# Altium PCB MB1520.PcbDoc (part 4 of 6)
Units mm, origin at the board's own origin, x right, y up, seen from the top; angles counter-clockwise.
Board outline 159 x 88 mm, 6 copper layers (Top Layer, Signal Layer 1, Signal Layer 2, Signal Layer 3, Signal Layer 4, Bottom Layer), stack 1.572 mm thick; 473 components, 377 nets, 1832 pads, 1378 vias.
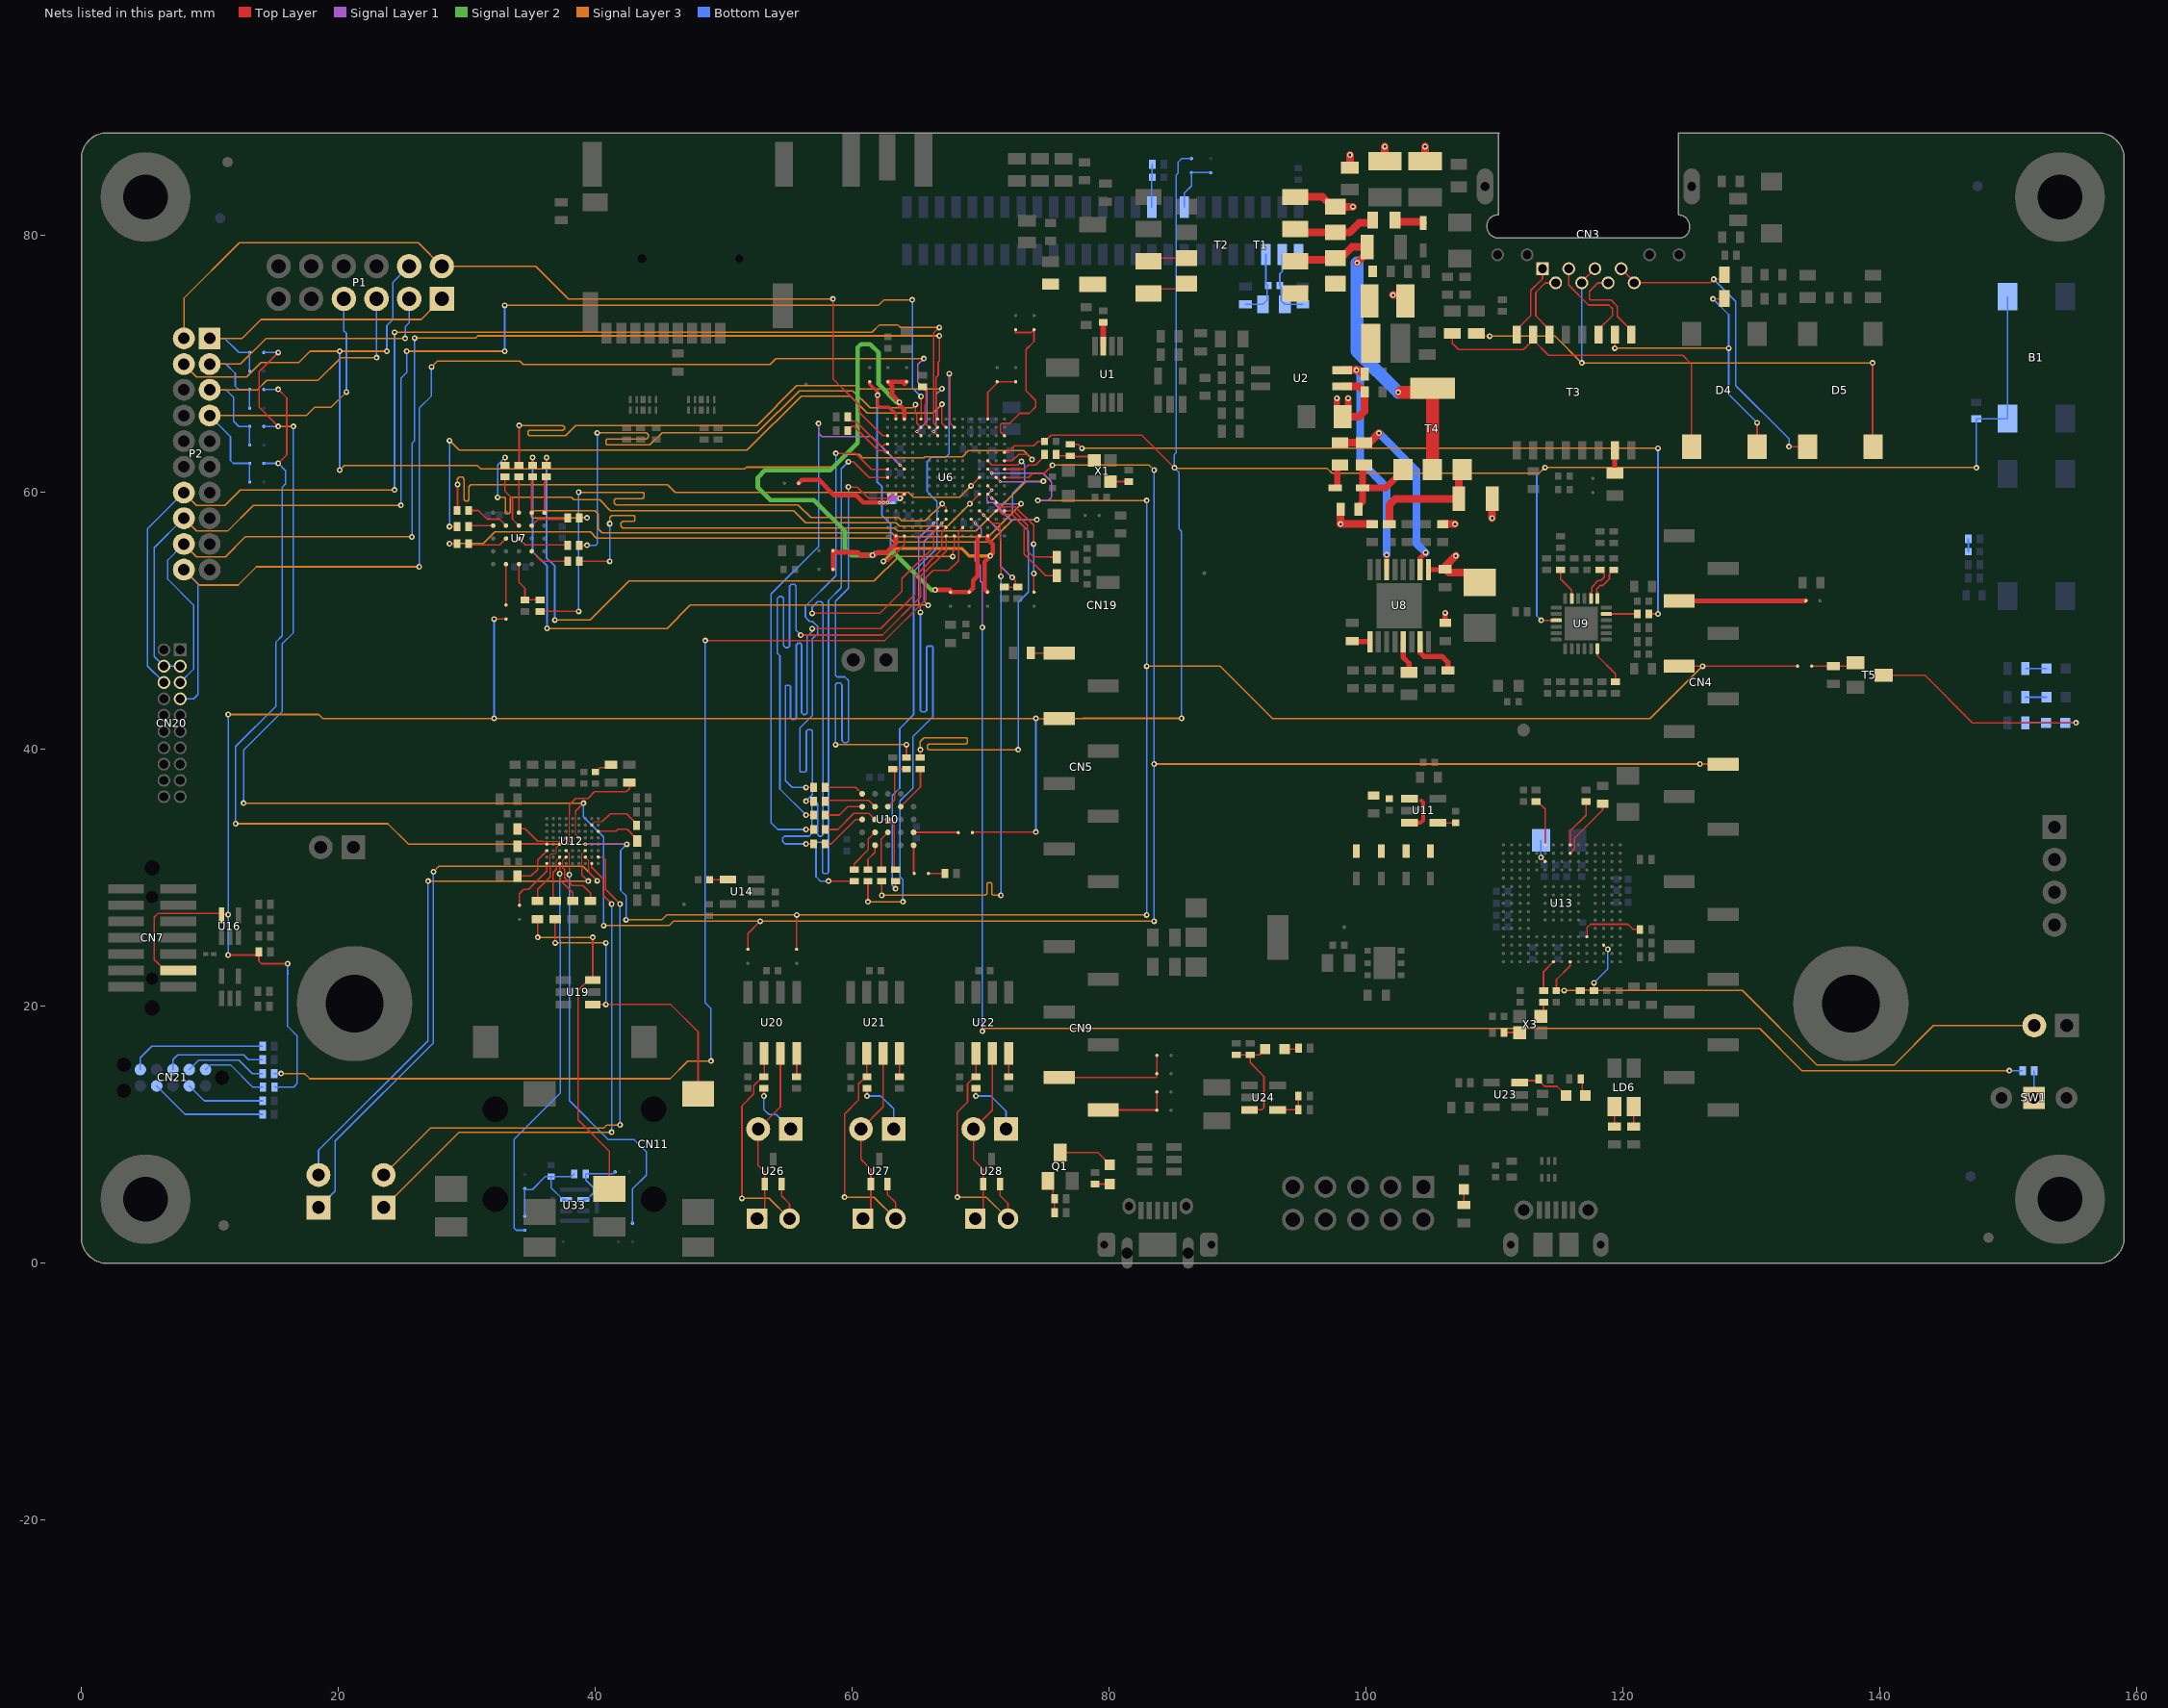
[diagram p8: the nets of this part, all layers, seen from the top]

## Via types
v1: diameter 0.45, hole 0.2, Top Layer to Bottom Layer, tented both sides, 1099 vias
v2: diameter 0.25, hole 0.1, Top Layer to Signal Layer 1, tented both sides, 217 vias
v3: diameter 0.25, hole 0.1, Signal Layer 4 to Bottom Layer, tented both sides, 53 vias
v4: diameter 0.6, hole 0.3, Top Layer to Bottom Layer, tented both sides, 9 vias

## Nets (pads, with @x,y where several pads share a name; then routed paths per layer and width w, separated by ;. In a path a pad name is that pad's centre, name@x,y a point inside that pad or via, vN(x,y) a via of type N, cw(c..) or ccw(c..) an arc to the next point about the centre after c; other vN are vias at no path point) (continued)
NetC69_2: C69.2 R85.2 | length 1.4
  Top Layer w0.12: C69.2@40.025,38.25 40.375,38.6 41,38.6 R85.2@41.225,38.825
NetC71_2: C71.2 U13.J14 | length 4.9
  Top Layer w0.127: U13.J14@115.883,31.927 116.225,32.269 116.225,33.1 118.411,35.286 C71.2@118.411,35.764
NetC73_1: C73.1 C75.2 D8.2 D9.2 D10.2 D11.2 U11.1 U11.3 | length 2.7
  Top Layer w0.3: U11.3@103.386,34.289 104.214,34.289 104.425,34.5 104.425,35.875 104.275,36.025
NetC76_2: C76.2 U11.4 | length 1.4
  Top Layer w0.12: U11.4@105.586,34.289 C76.2@106.986,34.289
NetC78_1: C78.1 U12.E6 | length 4.3
  Top Layer w0.09: 35.945,32.875 37.475,32.875 U12.E6@37.725,33.125
  Top Layer w0.1: C78.1@33.95,33.825 34.55,33.825 35.5,32.875 35.945,32.875
NetC79_2: C79.2 U12.F1 | length 3.5
  Top Layer w0.1: U12.F1@40.225,33.625 41.605,33.625 41.755,33.775 42.475,33.775 43.275,32.975 C79.2@43.275,32.875
NetC80_2: C80.2 U12.D9 | length 2.3
  Top Layer w0.1: C80.2@33.95,32.45 34.125,32.625 U12.D9@36.225,32.625
NetC84_2: C84.2 U12.C9 | length 3.5
  Top Layer w0.1: C84.2@33.95,30.15 35,30.15 35.5,30.65 35.5,31.4 U12.C9@36.225,32.125
NetC85_2: C85.2 U14.4 | length 1.4
  Top Layer w0.12: C85.2@48.9,29.875 U14.4@50.325,29.875
NetC89_1: C89.1 U12.D7 | length 5.3
  Top Layer w0.09: 36.475,30.8 36.475,31.775 36.575,31.875 36.875,31.875 36.975,31.975 36.975,32.375 U12.D7@37.225,32.625
  Top Layer w0.1: C89.1@35.5,28.2 35.5,29.1 36.475,30.075 36.475,30.8
NetC89_2: C89.2 CN11.4 U19.6 | length 27
  Top Layer w0.12: C89.2@35.5,26.8 35.525,26.775 v1(35.525,25.375) ; v1(39.8,25.375) U19.6@39.8,22.05 39.45,22.05 38.65,21.25 38.65,11.175 41.1,8.725 CN11.4@41.1,5.8
  Signal Layer 3 w0.12: v1(35.525,25.375) v1(39.8,25.375)
NetC90_1: C90.1 U12.B7 | length 3.7
  Top Layer w0.09: 36.975,30.8 36.975,31.375 U12.B7@37.225,31.625
  Top Layer w0.1: C90.1@36.875,28.2 36.7,28.375 36.7,30.425 36.975,30.7 36.975,30.8
NetC90_2: C90.2 CN11.6 U19.4 | length 24.5
  Top Layer w0.12: v1(36.875,24.95) C90.2@36.875,26.8 ; U19.4@39.8,20.15 45.875,20.15 48,18.025 CN11.6@48,13.2
  Signal Layer 3 w0.12: v1(36.875,24.95) v1(40.825,24.95)
  Bottom Layer w0.12: v1(40.825,20.15) v1(40.825,24.95)
NetC91_2: C91.2 SB37.2 U12.A7 | length 33.3
  Top Layer w0.1: U12.A7@37.225,31.125 37.225,29.875 38.25,28.85 C91.2@38.25,28.2
  Bottom Layer w0.1: 37.225,27.5 v1(37.225,30.325)
  Bottom Layer w0.12: SB37.2@34.512,2.577 33.848,2.577 33.675,2.75 33.675,9.65 37.28,13.255 37.28,25.118 37.225,25.173 37.225,27.5
NetC92_2: C92.2 U12.B6 | length 4.9
  Top Layer w0.09: 37.475,30.8 37.475,31.375 U12.B6@37.725,31.625
  Top Layer w0.1: 37.475,30.8 37.6,30.675 37.6,30 38.2,29.4 39.05,29.4 39.625,28.825 C92.2@39.625,28.2
NetC104_2: C104.2 JP3.2 U13.J1 | length 43.5
  Top Layer w0.12: C104.2@114.811,21.239 v1(115.411,21.239)
  Top Layer w0.127: C104.2@114.811,21.239 114.811,22.086 115.883,23.158 U13.J1@115.883,23.477
  Signal Layer 3 w0.12: v1(115.411,21.239) 129.286,21.239 135.075,15.45 141.1,15.45 144.167,18.517 JP3.2@152.007,18.517
NetC117_2: C117.2 CN19.32 R136.1 | length 3.3
  Bottom Layer w0.127: CN19.32@83.31,82.217 83.31,84.485 C117.2@83.35,84.525 R136.1@83.35,85.55
NetC118_1: C118.1 C119.2 CN19.45 R138.2 | length 5.5
  Bottom Layer w0.127: R138.2@90.6,74.65 C119.2@91.975,74.65 92.3,74.975 92.3,76.025 C118.1@92.375,76.1 92.2,76.275 CN19.45@92.2,78.531
NetC118_2: C118.2 C119.1 CN19.47 CN19.49 R137.2 | length 6.8
  Bottom Layer w0.127: CN19.49@94.74,78.531 CN19.47@93.47,78.531 93.47,77.195 93.275,77 C118.2@93.275,76.1 93.4,75.975 93.4,74.925 C119.1@93.675,74.65 R137.2@95.075,74.65
NetC130_1: C130.1 SB11.2 U6.E15 U6.F13 | length 10.6
  Top Layer w0.3: v1(63.725,59.55) U6.F13@64.05,59.875
  Top Layer w0.35: SB11.2@55.825,60.725 56.075,60.975 57.425,60.975 58.6,59.8 60.3,59.8 60.875,59.225 v2(62.15,59.225) v2(62.45,59.225) v2(62.75,59.225)
  Signal Layer 1 w0.35: v2(62.15,59.225) v2(62.45,59.225) v2(62.75,59.225) 63.075,59.55 v1(63.725,59.55)
  Bottom Layer w0.45: C130.1@63.025,59.55 v1(63.725,59.55)
NetC138_1: C138.1 R140.1 | length 1
  Bottom Layer w0.12: C138.1@146.875,55.4 R140.1@146.875,56.4
NetC142_2: C142.2 U13.F13 | length 1.8
  Top Layer w0.12: v1(113.608,31.602) U13.F13@113.933,31.277
  Bottom Layer w0.1: v1(113.608,31.602) 113.608,32.908 C142.2@113.625,32.925
NetC158_1: C158.1 R154.2 SB36.1 SB37.1 U33.1 | length 8.9
  Bottom Layer w0.12: SB37.1@34.512,3.677 SB36.1@34.512,5.819 34.581,5.75 35.1,5.75 36.098,6.748 C158.1@36.549,6.748 ; U33.1@37.724,4.973 37.477,4.973 36.549,5.901 C158.1@36.549,6.748 ; R154.2@38.36,6.965 38.143,6.748 C158.1@36.549,6.748
NetCN3_1: CN3.1 T3.16 | length 5.9
  Top Layer w0.13: T3.16@111.741,72.299 111.741,72.691 112.821,73.771 112.821,75.725 113.73,76.634 CN3.1@113.73,77.425
NetCN3_2: CN3.2 T3.14 | length 5.6
  Top Layer w0.13: T3.14@114.281,72.299 114.281,72.669 113.202,73.748 113.202,75.567 113.959,76.325 CN3.2@114.75,76.325
NetCN3_3: CN3.3 T3.11 | length 7.9
  Top Layer w0.13: CN3.3@115.77,77.425 115.77,76.141 117.311,74.6 118.9,74.6 119.171,74.329 119.171,73.771 118.091,72.691 T3.11@118.091,72.299
NetCN3_4: CN3.4 CN3.5 D5.2 R15.2 | length 46.1
  Top Layer w0.12: R15.2@108.586,72.389 108.801,72.175 v1(109.625,72.175) ; CN3.4@116.79,76.325 116.79,76.405 CN3.5@117.81,77.425 ; v1(139.425,70.085) 139.425,63.611 D5.2@139.461,63.574
  Signal Layer 3 w0.12: v1(109.625,72.175) 114.7,72.175 v1(116.79,70.085) v1(139.425,70.085)
  Bottom Layer w0.12: v1(116.79,70.085) CN3.4@116.79,76.325
NetCN3_6: CN3.6 T3.9 | length 7.4
  Top Layer w0.13: CN3.6@118.83,76.325 118.05,76.325 117.375,75.65 117.375,75.075 117.469,74.981 119.058,74.981 119.552,74.487 119.552,73.723 120.631,72.644 T3.9@120.631,72.299
NetCN3_7: CN3.7 CN3.8 D5.1 R9.2 | length 25.7
  Top Layer w0.12: CN3.7@119.85,77.425 120.87,76.405 CN3.8@120.87,76.325 126.775,76.325 v1(127.05,76.6) 127.529,76.6 R9.2@127.888,76.959 ; v1(132.923,63.574) D5.1@134.361,63.574
  Bottom Layer w0.12: v1(127.05,76.6) 128.775,74.875 128.775,68.325 132.923,64.177 v1(132.923,63.574)
NetCN4_8: CN4.8 SB23.1 | length 9.9
  Top Layer w0.127: CN4.8@124.372,51.564 CN4.8@124.375,51.567
  Top Layer w0.35: CN4.8@124.372,51.564 134.189,51.564 SB23.1@134.225,51.6
NetCN5_1: CN5.1 R72.2 | length 2.2
  Top Layer w0.12: R72.2@73.911,47.514 76.098,47.514 CN5.1@76.112,47.5
NetCN9_5: CN9.5 SB31.2 SB32.2 | length 9.3
  Top Layer w0.12: CN9.5@76.112,14.48 83.63,14.48 83.711,14.561 SB32.2@83.711,14.764 SB31.2@83.711,16.189
NetCN9_6: CN9.6 SB33.2 SB34.2 | length 5.6
  Top Layer w0.12: CN9.6@79.541,11.94 83.685,11.94 SB34.2@83.711,11.914 SB33.2@83.711,13.339
NetCN12_1: CN12.1 U12.B3 | length 45.5
  Top Layer w0.09: U12.B3@39.225,31.625 39.475,31.375 39.475,30.8
  Top Layer w0.1: 39.475,30.8 39.475,30.45 v1(40.15,29.775)
  Signal Layer 3 w0.12: v1(27.4,30.475) 27.825,30.9 33.2,30.9 39.025,30.9 v1(40.15,29.775)
  Bottom Layer w0.12: CN12.1@18.453,4.343 19.75,5.64 19.75,9.525 27.4,17.175 v1(27.4,30.475)
NetCN12_2: CN12.2 U12.C3 | length 41.5
  Top Layer w0.09: 38.975,30.85 38.975,31.875 U12.C3@39.225,32.125
  Top Layer w0.1: 38.975,30.85 38.975,30.225 v1(39.45,29.75)
  Signal Layer 3 w0.12: v1(26.975,29.75) 33.2,29.75 v1(39.45,29.75)
  Bottom Layer w0.12: CN12.2@18.453,6.883 18.453,8.803 26.975,17.325 v1(26.975,29.75)
NetCN13_1: CN13.1 U12.A2 | length 41.7
  Top Layer w0.1: U12.A2@39.725,31.125 39.725,30.825 40.6,29.95 40.6,28.65 v1(41.275,27.975)
  Signal Layer 3 w0.12: CN13.1@23.533,4.343 29.39,10.2 v1(41.275,10.2)
  Bottom Layer w0.1: 41.275,27.5 v1(41.275,27.975)
  Bottom Layer w0.12: v1(41.275,10.2) 41.275,27.5
NetCN13_2: CN13.2 U12.B1 | length 41.8
  Top Layer w0.09: U12.B1@40.225,31.625 40.625,31.625 40.8,31.45
  Top Layer w0.1: 40.8,31.45 40.8,29.1 v1(41.925,27.975)
  Signal Layer 3 w0.12: CN13.2@23.533,6.883 27.2,10.55 40.675,10.55 40.9,10.775 v1(41.925,10.775)
  Bottom Layer w0.1: 41.925,27.5 v1(41.925,27.975)
  Bottom Layer w0.12: v1(41.925,10.775) 41.925,27.5
NetCN16_1: CN16.1 JP4.2 U20.7 U26.1 | length 14.1
  Top Layer w0.12: CN16.1@52.58,3.475 53.2,4.095 U26.1@53.2,6.175 53.2,7.1 52.68,7.62 JP4.2@52.68,10.45 54.41,12.18 U20.7@54.41,16.35
NetCN16_2: CN16.2 R119.1 U20.6 U26.2 | length 19.4
  Top Layer w0.12: v1(51.41,5.06) 51.41,12.265 52.335,13.19 52.335,13.835 53.025,14.525 R119.1@53.125,14.525 53.14,14.54 U20.6@53.14,16.35 ; U26.2@54.5,6.175 54.5,5.25 55.12,4.63 CN16.2@55.12,3.475
  Signal Layer 3 w0.12: v1(51.41,5.06) 53.535,5.06 CN16.2@55.12,3.475
NetCN17_1: CN17.1 JP5.2 U21.7 U27.1 | length 14.2
  Top Layer w0.12: CN17.1@60.83,3.475 61.45,4.095 U27.1@61.45,6.175 61.45,7.325 60.68,8.095 JP5.2@60.68,10.45 62.41,12.18 U21.7@62.41,16.35
NetCN17_2: CN17.2 R121.1 U21.6 U27.2 | length 19.6
  Top Layer w0.12: v1(59.4,5.15) 59.4,11.625 60.5,12.725 60.5,13.975 61.05,14.525 R121.1@61.15,14.525 61.14,14.535 U21.6@61.14,16.35 ; U27.2@62.75,6.175 62.75,5.35 63.37,4.73 CN17.2@63.37,3.475
  Signal Layer 3 w0.12: v1(59.4,5.15) 61.695,5.15 CN17.2@63.37,3.475
NetCN18_1: CN18.1 JP6.2 U22.7 U28.1 | length 14.1
  Top Layer w0.12: CN18.1@69.58,3.475 70.2,4.095 U28.1@70.2,6.175 70.2,7.325 69.43,8.095 JP6.2@69.43,10.45 70.91,11.93 U22.7@70.91,16.35
NetCN18_2: CN18.2 R123.1 U22.6 U28.2 | length 19.5
  Top Layer w0.12: v1(68.175,5.15) 68.175,11.75 68.975,12.55 68.975,13.975 69.525,14.525 R123.1@69.625,14.525 69.64,14.54 U22.6@69.64,16.35 ; U28.2@71.5,6.175 71.5,5.275 72.12,4.655 CN18.2@72.12,3.475
  Signal Layer 3 w0.12: v1(68.175,5.15) 70.445,5.15 CN18.2@72.12,3.475
NetCN19_36: CN19.36 SB43.1 SB44.1 | length 4.4
  Bottom Layer w0.12: CN19.36@85.85,82.217 85.85,83.325 86.4,83.875 SB44.1@86.4,84.9 SB43.1@87.9,84.9
NetCN21_2: CN21.2 R152.2 | length 6.2
  Bottom Layer w0.12: CN21.2@8.395,13.815 9.56,12.65 R152.2@14.1,12.65
NetCN21_4: CN21.4 R153.2 | length 9.2
  Bottom Layer w0.12: CN21.4@5.855,13.815 8.07,11.6 R153.2@14.1,11.6
NetCN21_6: CN21.6 R147.2 | length 10.8
  Bottom Layer w0.12: CN21.6@4.585,15.085 4.585,16.01 5.475,16.9 R147.2@14.1,16.9
NetCN21_8: CN21.8 R148.2 | length 8.1
  Bottom Layer w0.12: CN21.8@7.125,15.085 7.125,15.85 7.5,16.225 12.625,16.225 13,15.85 R148.2@14.1,15.85
NetCN21_9: CN21.9 R150.2 | length 6.4
  Bottom Layer w0.12: CN21.9@8.395,15.085 9.135,15.825 12.25,15.825 13.3,14.775 R150.2@14.1,14.775
NetCN21_10: CN21.10 R151.2 | length 5.3
  Bottom Layer w0.12: CN21.10@9.665,15.085 10.035,15.455 11.595,15.455 13.325,13.725 R151.2@14.125,13.725
NetD3_1: D3.1 R4.1 | length 2.3
  Top Layer w0.6: R4.1@102.261,81.214 102.401,81.075 104.346,81.075 D3.1@104.436,80.984
NetD4_1: D4.1 R14.2 T3.15 | length 27.5
  Top Layer w0.12: R14.2@106.711,72.389 106.711,71.614 107.2,71.125 112.25,71.125 T3.15@113.011,71.886 ; T3.15@113.011,72.299 T3.15@113.011,71.886 ; D4.1@125.336,63.574 125.336,69.989 124.65,70.675 114.2,70.675 113.011,71.864 T3.15@113.011,71.886
NetD4_2: D4.2 R12.2 T3.10 | length 23.7
  Top Layer w0.12: v1(119.361,71.239) T3.10@119.361,72.299 ; v1(127,75.075) 127.872,75.075 R12.2@127.886,75.089 ; D4.2@130.436,63.574 v1(130.436,65.439)
  Signal Layer 3 w0.12: v1(119.361,71.239) v1(128.225,71.239)
  Bottom Layer w0.12: v1(127,75.075) 128.225,73.85 128.225,67.65 v1(130.436,65.439)
NetD6_1: D6.1 R34.2 R44.2 T4.1 | length 7.4
  Top Layer w0.508: R44.2@99.411,58.689 99.411,58.961 99.731,59.281 D6.1@99.731,60.364 ; R34.2@99.836,62.139 99.731,62.034 D6.1@99.731,60.364 ; T4.1@102.869,61.778 102.869,61.703 101.53,60.364 D6.1@99.731,60.364
NetD6_2: D6.2 R33.1 | length 1.9
  Top Layer w0.508: D6.2@97.591,60.364 97.761,60.534 97.761,61.939 R33.1@97.961,62.139
NetJP4_1: JP4.1 R119.2 | length 4.4
  Top Layer w0.12: v1(53.125,13.025) R119.2@53.125,13.625
  Bottom Layer w0.12: v1(53.125,13.025) 53.125,11.975 53.525,11.575 54.095,11.575 JP4.1@55.22,10.45
NetJP5_1: JP5.1 R121.2 | length 4.7
  Top Layer w0.12: v1(61.15,13.025) R121.2@61.15,13.625
  Bottom Layer w0.12: v1(61.15,13.025) 62.225,13.025 63.22,12.03 JP5.1@63.22,10.45
NetJP6_1: JP6.1 R123.2 | length 4.8
  Top Layer w0.12: v1(69.625,13.025) R123.2@69.625,13.625
  Bottom Layer w0.12: v1(69.625,13.025) 70.8,13.025 71.97,11.855 JP6.1@71.97,10.45
NetLD1_2: LD1.2 R144.2 | length 1.6
  Bottom Layer w0.12: R144.2@151.325,44.075 LD1.2@152.95,44.075
NetLD2_2: LD2.2 R143.2 | length 1.6
  Bottom Layer w0.12: R143.2@151.325,46.3 LD2.2@152.95,46.3
NetLD3_1: LD3.1 R126.1 | length 1.4
  Top Layer w0.12: R126.1@116.711,14.364 116.825,14.251 116.825,13.301 LD3.1@117.061,13.064
NetLD3_2: LD3.2 R125.1 U23.3 | length 4.3
  Top Layer w0.12: U23.3@111.961,14.064 112.122,14.225 113.297,14.225 R125.1@113.436,14.364 113.436,14.239 113.9,13.775 114.851,13.775 LD3.2@115.561,13.064
NetLD4_1: LD4.1 R132.1 | length 1.2
  Top Layer w0.12: R132.1@78.9,6.175 LD4.1@80.05,6.175
NetLD4_2: LD4.2 Q1.3 | length 4.3
  Top Layer w0.12: Q1.3@76.175,8.625 79.125,8.625 80.05,7.7 LD4.2@80.05,7.675
NetLD5_1: LD5.1 R134.2 | length 1.2
  Top Layer w0.12: R134.2@107.611,4.539 LD5.1@107.611,5.764
NetLD6_2: LD6.2 R131.1 | length 1.5
  Top Layer w0.127: R131.1@120.836,10.664 LD6.2@120.836,12.189
NetLD6_3: LD6.3 R130.1 | length 1.5
  Top Layer w0.127: R130.1@119.336,10.664 LD6.3@119.336,12.189
NetLD7_1: LD7.1 R118.1 | length 1.1
  Top Layer w0.12: LD7.1@93.651,16.688 94.661,16.688 R118.1@94.737,16.764
NetLD7_2: LD7.2 R116.1 R117.1 U24.3 | length 8.2
  Top Layer w0.12: R116.1@89.9,16.225 R117.1@90.975,16.225 ; U24.3@90.925,11.95 91.875,11.95 92.05,12.125 92.05,14.55 90.975,15.625 R117.1@90.975,16.225 ; LD7.2@92.151,16.688 91.688,16.225 R117.1@90.975,16.225
NetLD8_1: LD8.1 R145.1 | length 1.6
  Bottom Layer w0.12: R145.1@151.325,42.075 LD8.1@152.925,42.075
NetLD8_2: LD8.2 T5.3 | length 17.3
  Top Layer w0.12: T5.3@140.3,45.789 143.486,45.789 147.2,42.075 v1(155.25,42.075)
  Bottom Layer w0.12: LD8.2@154.425,42.075 v1(155.25,42.075)
NetQ1_1: Q1.1 R133.1 R135.1 | length 2.7
  Top Layer w0.12: Q1.1@75.225,6.425 75.625,6.025 75.625,5.15 R133.1@75.75,5.025 R135.1@75.75,3.95
NetR16_2: R16.2 U1.3 | length 1.8
  Top Layer w0.45: R16.2@79.536,73.239 79.55,73.226 U1.3@79.55,71.4
NetR22_2: R22.2 U2.4 U8.14 | length 18.4
  Top Layer w0.35: U8.14@101.6,53.996 U8.14@101.6,54.2
  Top Layer w0.4: U8.14@101.6,54.2 v1(101.6,55.15)
  Top Layer w0.6: U2.4@98.136,69.524 v1(99.25,69.524) 99.451,69.524 99.761,69.214 R22.2@99.886,69.214
  Bottom Layer w0.6: v1(99.25,69.524) 99.525,69.249 99.525,62.475 101.6,60.4 v1(101.6,55.15)
NetR24_2: R24.2 U6.P10 | length 3.3
  Top Layer w0.1: R24.2@65.725,68.225 65.725,66.9 65.675,66.85 65.675,65.4 U6.P10@66,65.075
NetR25_2: R25.2 U6.M15 | length 4.1
  Top Layer w0.13: R25.2@59.65,65.9 59.997,65.553 60.272,65.553 62.185,63.641 62.426,63.641 62.56,63.775 U6.M15@62.75,63.775
NetR32_2: R32.2 U6.L15 | length 4.1
  Top Layer w0.13: R32.2@59.65,64.825 59.997,65.172 60.114,65.172 62.027,63.26 62.325,63.26 62.426,63.26 62.56,63.125 U6.L15@62.75,63.125
NetR33_2: R33.2 R34.1 U8.10 | length 15.6
  Top Layer w0.4: U8.10@104.201,53.996 104.201,54.901 v1(104.625,55.325)
  Top Layer w0.6: R33.2@97.961,63.889 R34.1@99.836,63.889 100.264,63.889 v1(101,64.625)
  Bottom Layer w0.6: v1(101,64.625) 103.925,61.7 103.925,56.025 v1(104.625,55.325)
NetR35_2: R35.2 R36.1 X1.3 | length 3.2
  Top Layer w0.127: R36.1@75.875,62.975 76,62.85 R35.2@76.975,62.85 77.025,62.8 78.55,62.8 X1.3@78.85,62.5
NetR36_2: R36.2 U6.J1 | length 3.7
  Top Layer w0.127: U6.J1@71.85,61.825 73.4,61.825 73.725,62.15 74.275,62.15 74.975,62.85 R36.2@74.975,62.975
NetR37_2: R37.2 U6.F4 | length 45.7
  Top Layer w0.127: R37.2@32.975,62.125 v1(32.975,62.725) ; v1(69.15,59.125) U6.F4@69.9,59.875
  Signal Layer 3 w0.102: v1(32.4,59.625) 32.925,59.625 33,59.55 33,58.475 33.1,58.375 33.275,58.375 33.375,58.475 33.375,59.525 33.475,59.625 38.15,59.625 38.326,59.449 38.939,59.449 38.94,59.45 40.331,59.45 41.181,58.6 55.432,58.6 56.375,57.657 63.424,57.657 63.683,57.398 67.423,57.398 v1(69.15,59.125)
  Bottom Layer w0.127: v1(32.4,59.625) 32.4,62.15 v1(32.975,62.725)
NetR38_1: R38.1 U6.N9 | length 48
  Top Layer w0.127: R38.1@34.05,62.125 34.076,62.151 v1(34.076,65.226) ; v2(66.325,64.75) U6.N9@66.65,64.425
  Signal Layer 1 w0.1: v2(66.325,64.75) 66.539,64.963 66.539,67.639 v1(66.975,68.075)
  Signal Layer 3 w0.102: v1(34.076,65.226) 37.475,65.226 37.6,65.101 37.6,64.95 37.475,64.825 34.85,64.825 34.75,64.725 34.75,64.525 34.85,64.425 37.674,64.425 38.475,65.226 52.576,65.226 55.675,68.325 60.325,68.325 60.575,68.075 v1(66.975,68.075)
NetR39_1: R39.1 U6.C8 | length 52.3
  Top Layer w0.127: R39.1@35.125,62.125 v1(35.125,62.725) ; v2(66.975,57.6) U6.C8@67.3,57.925
  Signal Layer 1 w0.1: v1(65.9,51.225) 65.578,51.547 65.578,56.203 v2(66.975,57.6)
  Signal Layer 3 w0.102: v1(36.25,49.425) 45.575,49.425 47.401,51.251 65.874,51.251 v1(65.9,51.225)
  Bottom Layer w0.127: v1(35.125,62.725) 35.125,55.396 36.25,54.271 v1(36.25,49.425)
NetR40_1: R40.1 U6.A7 | length 48.2
  Top Layer w0.1: v1(67.825,55.025) 67.825,55.413 67.95,55.538 U6.A7@67.95,56.625
  Top Layer w0.127: R40.1@36.2,62.125 v1(36.2,62.725)
  Signal Layer 3 w0.102: v1(36.85,50.075) 39.6,50.075 42.625,53.1 61.7,53.1 63.625,55.025 v1(67.825,55.025)
  Bottom Layer w0.127: v1(36.2,62.725) 36.2,54.925 36.85,54.275 v1(36.85,50.075)
NetR41_1: R41.1 X1.1 | length 1.4
  Top Layer w0.12: X1.1@80.1,60.85 R41.1@81.525,60.85
NetR42_1: R42.1 T3.7 | length 1.8
  Top Layer w0.381: R42.1@119.361,61.514 T3.7@119.361,63.279
NetR43_2: R43.2 R47.2 T4.3 | length 9.5
  Top Layer w0.6: R47.2@101.811,57.539 101.811,59.061 102.264,59.514 R43.2@107.211,59.514 T4.3@107.211,61.52
  Top Layer w0.762: T4.3@107.211,61.52 T4.3@107.469,61.778
NetR45_2: R45.2 U6.H4 | length 47
  Top Layer w0.127: R45.2@29.25,58.6 29.275,58.625 v1(29.275,60.625) ; v1(69.25,60.525) U6.H4@69.9,61.175
  Signal Layer 3 w0.102: v1(29.275,60.625) 29.275,61.05 29.425,61.2 29.675,61.2 29.8,61.075 29.8,59.45 29.9,59.35 30.075,59.35 30.175,59.45 30.175,60.475 30.325,60.625 45.625,60.625 46.225,60.025 64.375,60.025 64.75,59.65 68.375,59.65 v1(69.25,60.525)
NetR46_2: R46.2 U6.F3 | length 48.9
  Top Layer w0.127: R46.2@38.75,58.025 v1(39.35,58.025) ; U6.F3@70.55,59.875 v2(70.875,59.55)
  Signal Layer 1 w0.1: v2(70.875,59.55) 70.98,59.445 71.058,59.445 71.378,59.125 v1(73.15,59.125)
  Signal Layer 3 w0.102: v1(39.35,58.025) 35.15,58.025 35.025,58.15 35.025,58.425 35.175,58.575 39.975,58.575 40.225,58.325 40.225,57.15 40.522,56.853 63.091,56.853 63.369,56.575 70.6,56.575 v1(73.15,59.125)
NetR48_1: R48.1 U6.P8 | length 50.4
  Top Layer w0.1: v1(66.975,66.875) 66.975,65.402 66.974,65.401 U6.P8@67.3,65.075
  Top Layer w0.127: v1(28.65,57.35) R48.1@29.25,57.35
  Signal Layer 3 w0.102: v1(28.65,64.049) 29.399,63.3 51.819,63.3 56.019,67.5 59.875,67.5 61.177,66.198 66.298,66.198 v1(66.975,66.875)
  Bottom Layer w0.127: v1(28.65,57.35) v1(28.65,64.049)
NetR52_2: R52.2 U6.G3 | length 53.7
  Top Layer w0.127: v1(28.65,56.025) R52.2@29.25,56.025 ; U6.G3@70.55,60.525 v2(70.875,60.2)
  Signal Layer 1 w0.1: v2(70.875,60.2) 70.475,59.8 70.475,59.325 70.575,59.225 70.967,59.225 71.17,59.022 72.317,57.875 v1(74.375,57.875)
  Signal Layer 3 w0.102: v1(28.65,56.025) 31.275,56.025 32.175,56.925 39.625,56.925 40.099,56.451 62.925,56.451 63.226,56.15 70.744,56.15 72.469,57.875 v1(74.375,57.875)
NetR53_2: R53.2 U6.P11 | length 46.5
  Top Layer w0.1: v1(64.925,66.85) 64.925,66.175 65.025,66.075 65.025,65.4 U6.P11@65.35,65.075
  Top Layer w0.127: R53.2@38.75,55.9 v1(39.35,55.9)
  Signal Layer 3 w0.102: v1(40.15,64.65) 43.975,64.65 44.125,64.5 44.125,64.3 43.975,64.15 40.925,64.15 40.825,64.05 40.825,63.8 40.923,63.702 44.252,63.702 45.2,64.65 52.6,64.65 55.873,67.923 60.052,67.923 61.375,66.6 64.675,66.6 v1(64.925,66.85)
  Bottom Layer w0.127: v1(39.35,55.9) 40.025,55.9 40.15,56.025 v1(40.15,64.65)
NetR56_2: R56.2 U9.11 | length 2.6
  Top Layer w0.12: R56.2@115.125,53.975 115.125,53.275 116,52.4 U9.11@116,51.75
NetR58_2: R58.2 U9.8 | length 2.9
  Top Layer w0.13: U9.8@117.5,51.75 117.5,52.24 117.559,52.3 117.559,52.642 118.067,53.15 118.272,53.15 118.547,53.425 118.547,53.628 R58.2@118.2,53.975
NetR59_2: R59.2 U9.7 | length 2.9
  Top Layer w0.13: U9.7@118,51.75 118,52.24 117.94,52.299 117.94,52.485 118.225,52.769 118.43,52.769 118.928,53.267 118.928,53.628 R59.2@119.275,53.975
NetR60_2: R60.2 U6.H2 | length 48
  Top Layer w0.1: U6.H2@71.2,61.175 v2(71.525,60.85)
  Top Layer w0.127: R60.2@38.75,54.65 v1(41.125,54.65)
  Signal Layer 1 w0.1: v2(71.525,60.85) 73.775,60.85 ; 73.775,60.85 74.85,60.85 v1(74.875,60.875)
  Signal Layer 3 w0.102: v1(41.125,57.575) 41.125,58.05 41.273,58.198 43,58.198 43.075,58.123 43.075,57.837 42.988,57.75 42.125,57.75 42,57.625 42,57.38 42.125,57.255 63.258,57.255 63.517,56.996 69.646,56.996 73.525,60.875 v1(74.875,60.875)
  Bottom Layer w0.127: v1(41.125,54.65) v1(41.125,57.575)
NetR63_2: R63.2 R64.2 U6.D4 | length 8.2
  Top Layer w0.1: R63.2@71.85,52.65 R64.2@72.9,52.65 72.7,52.85 72.7,53.15 v1(72.45,53.4)
  Top Layer w0.127: U6.D4@69.9,58.575 v2(70.225,58.25)
  Signal Layer 1 w0.1: v2(70.225,58.25) 71.55,56.925 71.55,54.266 v1@72.433,53.383
NetR66_1: R66.1 U6.D8 | length 47.7
  Top Layer w0.127: R66.1@35.7,50.745 35.706,50.75 v1(38.7,50.75) ; v1(67,59.125) 67.3,58.825 U6.D8@67.3,58.575
  Signal Layer 3 w0.102: v1(38.7,60.025) 43.7,60.025 43.8,59.925 43.8,59.65 43.675,59.525 41.575,59.525 41.475,59.425 41.475,59.167 41.6,59.042 55.792,59.042 56.775,58.059 63.591,58.059 63.85,57.8 65.675,57.8 v1(67,59.125)
  Bottom Layer w0.127: v1(38.7,50.75) v1(38.7,60.025)
NetR68_2: R68.2 U9.5 | length 2.4
  Top Layer w0.12: U9.5@118.7,50.55 R68.2@121.1,50.55
NetR69_1: R69.1 U8.1 | length 1.4
  Top Layer w0.4: R69.1@98.918,48.446 98.967,48.396 U8.1@100.301,48.396
NetR73_1: R73.1 SB25.1 T5.1 | length 3.5
  Top Layer w0.12: SB25.1@134.686,46.489 R73.1@136.361,46.489 137.836,46.489 T5.1@138.086,46.739
NetR74_2: R74.2 U8.5 | length 2.6
  Top Layer w0.4: U8.5@102.901,48.396 102.901,47.149 103.336,46.714 R74.2@103.336,46.014
NetR75_2: R75.2 U8.7 | length 3.9
  Top Layer w0.4: U8.7@104.201,48.396 104.201,47.549 104.499,47.251 105.899,47.251 106.361,46.789 R75.2@106.361,46.164
NetR80_1: R80.1 U9.24 | length 3.2
  Top Layer w0.12: U9.24@118,47.85 118,47.3 119.4,45.9 R80.1@119.4,45.275
NetR82_1: R82.1 U6.F14 | length 42
  Top Layer w0.1: v1(59.7,60.437) 60.388,60.437 61.275,59.55 62.8,59.55 63.125,59.875 U6.F14@63.4,59.875
  Top Layer w0.127: R82.1@64.225,39.375 v1(64.225,40.375)
  Signal Layer 3 w0.102: v1(58.7,40.375) v1(64.225,40.375)
  Bottom Layer w0.1: 59.7,52.625 v1(59.7,60.437)
  Bottom Layer w0.127: v1(58.7,40.375) 58.7,45.075 58.8,45.175 59.063,45.175 59.2,45.037 59.2,40.675 59.35,40.525 59.575,40.525 59.7,40.65 59.7,45.375 59.425,45.65 58.825,45.65 58.7,45.775 58.7,51.546 59.7,52.546 59.7,52.625
NetR83_2: R83.2 U6.K3 | length 42.6
  Top Layer w0.1: U6.K3@70.55,62.475 70.875,62.15 72.9,62.15 v1(73.175,62.425)
  Top Layer w0.127: R83.2@65.3,39.375 v1(65.3,39.975)
  Signal Layer 3 w0.102: v1(65.3,39.975) 65.3,40.625 65.6,40.925 68.875,40.925 68.975,40.825 68.975,40.55 68.85,40.425 65.95,40.425 65.85,40.325 65.85,40.075 65.95,39.975 v1(72.925,39.975)
  Bottom Layer w0.127: v1(72.925,39.975) 72.925,51.475 73.704,52.253 73.704,56.997 72.475,58.225 72.475,59.925 73.425,60.875 73.425,62.175 v1(73.175,62.425)
NetR86_2: R86.2 U12.D4 U12.D5 | length 9.3
  Top Layer w0.09: 37.975,34.9 37.975,32.875 U12.D5@38.225,32.625
  Top Layer w0.1: 37.975,34.9 37.975,35.7 38.475,36.2 39.45,36.2 39.95,36.7 42.4,36.7 42.65,36.95 R86.2@42.65,37.425 ; U12.D5@38.225,32.625 U12.D4@38.725,32.625
NetR87_1: R87.1 U6.B8 | length 47.3
  Top Layer w0.1: 64.873,52.625 64.873,53.473 66.975,55.575 66.975,56.95 U6.B8@67.3,57.275
  Top Layer w0.127: v1(56.4,37.05) R87.1@57,37.05 ; v1(56.875,49.4) 62.208,49.4 64.873,52.065 64.873,52.625
  Bottom Layer w0.127: v1(56.4,37.05) 55.325,37.05 54.802,37.573 54.802,44.925 54.877,45 55.113,45 55.2,44.913 55.2,42.45 55.3,42.35 55.525,42.35 55.65,42.475 55.65,48.15 55.775,48.275 55.95,48.275 56.05,48.175 56.05,42.875 56.196,42.729 56.375,42.729 56.477,42.831 56.477,48.79 56.875,49.188 v1(56.875,49.4)
NetR88_1: R88.1 U13.F15 | length 3.7
  Top Layer w0.127: R88.1@113.236,35.939 113.361,35.939 113.933,35.368 U13.F15@113.933,32.577
NetR89_2: R89.2 U13.J15 | length 3.9
  Top Layer w0.127: U13.J15@115.883,32.577 115.883,33.658 117.111,34.886 R89.2@117.111,35.939
NetR91_1: R91.1 U6.J15 | length 41.8
  Top Layer w0.1: 59.175,63.05 60.275,63.05 61.5,61.825 U6.J15@62.75,61.825
  Top Layer w0.127: v1(56.4,35.975) R91.1@57,35.975 ; v1(58.725,63.05) 59.175,63.05
  Bottom Layer w0.127: v1@56.418,35.975 56.418,35.993 56.904,36.479 56.904,41.425 56.779,41.55 56.55,41.55 56.425,41.425 56.425,38.325 56.35,38.25 56,38.25 55.925,38.325 55.925,41.675 56.904,42.654 56.904,48.613 57.302,49.011 57.302,49.577 56.904,49.975 56.675,49.975 56.35,50.3 56.35,51.15 58.725,53.525 v1(58.725,63.05)
NetR93_1: R93.1 U6.A8 | length 48.6
  Top Layer w0.1: 65.3,52.625 65.3,53.45 67.3,55.45 U6.A8@67.3,56.625
  Top Layer w0.127: v1(55.991,48.909) 62.352,48.909 65.3,51.857 65.3,52.625 ; v1(56.4,34.9) R93.1@57,34.9
  Bottom Layer w0.127: v1(55.991,48.909) 55.625,49.275 55.625,52.725 55.5,52.85 55.25,52.85 55.125,52.725 55.125,48.042 55.008,47.925 54.825,47.925 54.65,48.1 54.65,51.775 54.5,51.925 54.35,51.925 54.175,51.75 54.175,47.492 54.375,47.292 54.375,36.925 v1(56.4,34.9)
NetR94_2: R94.2 U12.G2 | length 4.3
  Top Layer w0.09: U12.G2@39.725,34.125 39.975,34.375 40.55,34.375
  Top Layer w0.1: 40.55,34.375 41.175,35 42.45,35 43.2,34.25 R94.2@43.2,34.1
NetR95_1: R95.1 U6.J13 | length 44.7
  Top Layer w0.127: v1(56.4,33.775) R95.1@57,33.775 ; v2(63.725,62.15) U6.J13@64.05,61.825
  Signal Layer 1 w0.1: v1(57.375,65.375) 57.375,64.625 57.647,64.353 61.522,64.353 v2(63.725,62.15)
  Bottom Layer w0.127: v1(56.4,33.775) 54.2,33.775 53.675,34.3 53.675,52.1 57.375,55.8 57.375,59.95 57.377,59.952 v1@57.377,65.375
NetR96_1: R96.1 U6.B9 | length 44.4
  Top Layer w0.1: 63.875,52.625 63.875,53.3 66.325,55.75 66.325,56.95 U6.B9@66.65,57.275
  Top Layer w0.127: v1(56.4,32.65) R96.1@57,32.65 ; v1(56.875,50.6) 62.164,50.6 63.875,52.311 63.875,52.625
  Bottom Layer w0.127: v1(56.4,32.65) 54.775,32.65 54.575,32.85 54.575,33.1 54.725,33.25 56.637,33.25 56.862,33.475 56.862,35.834 56.979,35.95 57.15,35.95 57.3,35.8 57.3,33.375 57.425,33.25 57.6,33.25 57.729,33.379 57.729,51.346 57.575,51.5 57.304,51.5 56.875,51.071 v1(56.875,50.6)
NetR98_1: R98.1 U6.H15 | length 45.2
  Top Layer w0.1: v1(59.7,62.4) 60.075,62.4 61.3,61.175 U6.H15@62.75,61.175
  Top Layer w0.127: v1(58.156,29.756) 60.144,29.756 R98.1@60.15,29.75
  Bottom Layer w0.127: v1@58.156,29.8 v1(58.156,29.756) 57.519,29.756 57.175,30.1 57.175,32.65 57.3,32.775 57.575,32.775 57.675,32.675 57.675,30.45 57.775,30.35 58.056,30.35 58.156,30.45 58.156,51.606 59.152,52.602 59.152,61.852 v1(59.7,62.4)
NetR99_1: R99.1 U6.C9 | length 46.9
  Top Layer w0.127: v1(61.225,28.15) R99.1@61.225,29.75 ; v2(66.325,57.6) U6.C9@66.65,57.925
  Signal Layer 1 w0.1: v1(65.3,50.675) 65.3,51.259 65.178,51.381 65.178,56.453 v2(66.325,57.6)
  Signal Layer 3 w0.102: v1(61.225,28.15) v1(63.95,28.15)
  Bottom Layer w0.127: v1(63.95,28.15) 63.95,29.875 63.725,30.1 63.725,36 64.725,37 64.725,41 66.275,42.55 66.275,47.975 66.2,48.05 65.875,48.05 65.8,47.975 65.8,43.05 65.675,42.925 65.425,42.925 65.3,43.05 v1(65.3,50.675)
NetR100_2: R100.2 U6.C3 | length 42.1
  Top Layer w0.1: U6.C3@70.55,57.925 70.875,57.6 71.425,57.6 71.5,57.525 71.5,56.333 71.575,56.258 v1(71.575,53.475)
  Top Layer w0.127: v1(62.3,28.65) R100.2@62.3,29.75
  Signal Layer 3 w0.102: v1(62.3,28.65) 70.35,28.65 70.475,28.775 70.475,29.525 70.575,29.625 70.775,29.625 70.875,29.525 70.875,28.75 70.975,28.65 v1(71.575,28.65)
  Bottom Layer w0.127: v1(71.575,28.65) v1(71.575,53.475)
NetR101_2: R101.2 U6.P7 | length 48.3
  Top Layer w0.1: v1(67.552,69.25) 67.565,69.237 67.565,68.904 67.625,68.844 67.625,65.4 U6.P7@67.95,65.075
  Top Layer w0.127: v1(63.375,29.15) R101.2@63.375,29.75
  Bottom Layer w0.127: v1(63.375,29.15) 63.125,29.4 63.125,36.425 63.7,37 63.7,41.625 64.775,42.7 64.775,53.85 66.592,55.667 66.592,59.308 65.825,60.075 65.825,62.425 66.15,62.75 67.275,62.75 67.537,63.011 67.537,66.787 67.552,66.802 v1(67.552,69.25)
NetR102_1: R102.1 SB27.2 | length 1.3
  Top Layer w0.127: SB27.2@65.925,30.35 R102.1@67.225,30.35
NetR105_2: R105.2 U13.L4 | length 5.1
  Top Layer w0.12: U13.L4@117.183,25.427 117.183,26.108 117.475,26.4 120.375,26.4 120.786,25.989 R105.2@121.311,25.989
NetR111_1: R111.1 X3.3 | length 1.2
  Top Layer w0.127: X3.3@113.611,19.214 113.811,19.414 R111.1@113.811,20.339
NetR111_2: R111.2 U13.G1 | length 2.6
  Top Layer w0.127: R111.2@113.811,21.239 113.811,22.705 U13.G1@114.583,23.477
NetR112_1: R112.1 R113.1 U13.N3 | length 5.2
  Top Layer w0.12: R112.1@116.661,21.239 R113.1@117.736,21.239 v1(117.736,21.839) ; U13.N3@118.483,24.777 v1(118.808,24.452)
  Bottom Layer w0.12: v1(117.736,21.839) 118.808,22.911 v1(118.808,24.452)
NetR115_2: R115.2 X3.1 | length 1.2
  Top Layer w0.127: R115.2@110.736,17.964 X3.1@111.961,17.964
NetR120_1: R120.1 U20.8 | length 1.8
  Top Layer w0.12: R120.1@55.675,14.525 55.68,14.53 U20.8@55.68,16.35
NetR122_1: R122.1 U21.8 | length 1.8
  Top Layer w0.12: R122.1@63.675,14.525 63.68,14.53 U21.8@63.68,16.35
NetR124_1: R124.1 U22.8 | length 1.8
  Top Layer w0.12: R124.1@72.175,14.525 72.18,14.53 U22.8@72.18,16.35
NetR128_2: R128.2 R129.2 U24.4 | length 2.7
  Top Layer w0.12: U24.4@93.125,11.95 R129.2@94.725,11.95 R128.2@94.725,13.025
NetR149_1: R149.1 U6.C5 | length 123
  Top Layer w0.127: U6.C5@69.25,57.925 v2(69.575,57.6)
  Signal Layer 1 w0.1: v2(69.575,57.6) 70.025,57.15 70.025,56.65 69.575,56.2 69.575,54.7 69.953,54.322 69.953,53.125 70.125,52.953 v1(70.125,49.5)
  Signal Layer 3 w0.12: v1(70.125,18.075) 70.33,18.28 130.645,18.28 133.925,15 v1(150.075,15)
  Bottom Layer w0.12: v1(70.125,18.075) v1(70.125,49.5) ; v1(150.075,15) R149.1@151.1,15
NetR149_2: R149.2 SW1.1 | length 2.1
  Bottom Layer w0.12: SW1.1@151.981,12.878 152,12.897 R149.2@152,15
NetR154_1: R154.1 SB35.2 U33.2 | length 5.1
  Bottom Layer w0.12: U33.2@39.074,4.973 39.349,4.973 39.85,5.474 39.85,5.9 39.26,6.49 R154.1@39.26,6.965 41.391,6.965 SB35.2@41.549,7.123
NetSB1_2: SB1.2 SB21.2 U6.A3 U6.A13 U6.R14 | length 34.5
  Top Layer w0.1: v1(62.425,54.65) 62.784,54.65 64.05,55.916 U6.A13@64.05,56.625
  Top Layer w0.25: SB1.2@61.35,68.625 61.35,68.45 61.975,67.825 v1(61.975,67.575) 61.975,66.795 62.126,66.644 62.856,66.644 63.4,66.1 U6.R14@63.4,65.725
  Top Layer w0.35: SB21.2@70.525,52.25 70.3,52.475 70.3,54.625 v1(70.75,55.075) 70.95,55.275 70.95,55.95 70.55,56.35 U6.A3@70.55,56.625
  Signal Layer 3 w0.25: v1(62.425,54.65) 63.425,55.65 68.525,55.65 69.1,55.075 v1(70.75,55.075)
  Bottom Layer w0.15: v1(61.975,67.575) 61.937,67.537 61.937,60.843 62.325,60.455 62.325,58.225 63,57.55 63,55.225 v1(62.425,54.65)
NetSB2_2: SB2.2 SB3.2 SB16.2 SB18.2 SB19.2 SB20.2 U6.A4 U6.A14 U6.R13 | length 61.9
  Top Layer w0.35: SB18.2@58.5,54.025 SB16.2@58.5,55.475 58.625,55.35 60.41,55.35 60.635,55.125 v1(61.575,55.125) 61.775,55.125 62,55.35 62.707,55.35 63.4,56.043 U6.A14@63.4,56.625 ; U6.R13@64.05,65.725 64.05,66.435 63.675,66.81 v1(63.675,67.025) 63.1,67.6 63.1,68.3 SB2.2@62.775,68.625 SB3.2@64.225,68.625 64.05,68.45 ; v1(66.45,52.425) 67.61,52.425 67.65,52.385 SB19.2@67.65,52.25 SB20.2@69.1,52.25 69.4,52.55 69.4,53.15 69.75,53.5 69.75,56.475 U6.A4@69.9,56.625
  Signal Layer 2 w0.35: v1(63.675,67.025) 63.45,67.025 62.05,68.425 62.05,70.89 61.385,71.555 60.68,71.555 60.425,71.3 60.425,63.875 58.275,61.725 53.2,61.725 52.65,61.175 52.65,60.375 53.625,59.4 57.025,59.4 59.425,57 59.425,55.625 59.925,55.125 v1(61.575,55.125) 61.75,55.3 63.275,55.3 66.15,52.425 v1(66.45,52.425)
NetSB4_2: SB4.2 SB5.2 U6.R3 | length 4.7
  Top Layer w0.1: SB4.2@71.275,68.625 SB5.2@72.725,68.625
  Top Layer w0.127: U6.R3@70.55,65.725 70.55,67.8 71.275,68.525 SB4.2@71.275,68.625
NetSB22_2: SB22.2 U6.E2 | length 8.9
  Top Layer w0.1: U6.E2@71.2,59.225 71.525,58.9 72.675,58.9 74.125,57.45 v1(74.125,56)
  Top Layer w0.127: v1(74.13,53.695) 74.13,52.27 SB22.2@74.15,52.25
  Bottom Layer w0.127: v1(74.13,53.695) v1@74.13,56
NetSB24_2: SB24.2 U7.A4 | length 3.2
  Top Layer w0.127: SB24.2@33.05,51.25 U7.A4@33.05,54.425
NetSB26_2: SB26.2 U10.A4 | length 3.5
  Top Layer w0.127: U10.A4@64.775,33.55 68.225,33.55 SB26.2@68.25,33.525
NetSB27_1: SB27.1 U10.A5 | length 2.2
  Top Layer w0.127: U10.A5@64.775,32.55 64.775,30.4 SB27.1@64.825,30.35
NetSB28_2: SB28.2 U12.A9 | length 4.3
  Top Layer w0.1: SB28.2@34.1,27.875 34.1,28.775 34.425,29.1 34.8,29.1 36.225,30.525 U12.A9@36.225,31.125
NetSB38_2: SB38.2 U12.C6 | length 33.2
  Top Layer w0.09: U12.C6@37.725,32.125 37.975,31.875 37.975,30.775
  Top Layer w0.1: v1(37.975,30.25) 37.975,30.775
  Bottom Layer w0.1: 37.975,27.5 v1(37.975,30.25)
  Bottom Layer w0.12: 37.975,27.5 37.975,12.675 41.025,9.625 43.025,9.625 43.975,8.675 43.975,6.875 42.899,5.799 SB38.2@42.899,3.123
NetSB41_1: SB41.1 SB42.1 U6.N1 | length 12.4
  Top Layer w0.1: U6.N1@71.85,64.425 71.55,64.725 71.55,65.275 71.675,65.4 72.275,65.4
  Top Layer w0.127: 72.275,65.4 73.05,66.175 73.775,66.175 74.275,66.675 74.275,67.175 73.525,67.925 73.525,71.128 74.15,71.753 SB42.1@74.15,72.675 73.938,72.463 72.675,72.463
NJTRST: R150.1 U6.B6 | length 93.7
  Top Layer w0.1: 65.75,52.625 65.75,53.383 66.292,53.925 67.505,53.925 68.275,54.695 68.275,56.95 U6.B6@68.6,57.275
  Top Layer w0.12: v1(48.55,48.485) 62.532,48.485 65.75,51.703 65.75,52.625
  Signal Layer 3 w0.12: v1(15.55,14.775) 17.375,14.775 17.775,14.375 45.825,14.375 47.2,15.75 v1(49,15.75)
  Bottom Layer w0.12: R150.1@15,14.775 v1(15.55,14.775) ; v1(48.55,48.485) 48.55,20.3 49,19.85 v1(49,15.75)
NRST: B1.3 B1.4 C32.2 CN5.3 CN7.12 R108.1 R151.1 SB24.1 SB26.1 SB44.2 U6.L1 U9.15 U16.5 U31.1 | length 297.4
  Top Layer w0.1: U6.L1@71.85,63.125 72.125,63.125 72.625,63.625 74.125,63.625 74.475,63.975 C32.2@74.975,63.975 75.425,64.425
  Top Layer w0.12: CN7.12@7.543,22.799 6.526,22.799 5.675,23.65 5.675,26.95 5.975,27.25 10.751,27.25 U16.5@10.911,27.089 10.972,27.15 v1(11.425,27.15) ; v1(11.425,24) R108.1@13.811,24 ; R108.1@13.811,24.239 R108.1@13.811,24 ; v1(16.05,23.325) 14.025,23.325 13.811,23.539 R108.1@13.811,24 ; v1(32.125,50.15) SB24.1@33.05,50.15 ; v1(74.295,42.42) CN5.3@76.112,42.42 ; 75.425,64.425 75.46,64.46 82.54,64.46 v1(85.075,61.925) ; v1(113.625,50.05) U9.15@114.8,50.05
  Top Layer w0.127: SB26.1@69.35,33.525 69.405,33.58 v1(74.295,33.58)
  Signal Layer 3 w0.12: v1(11.425,42.725) 18.475,42.725 18.78,42.42 v1(32.125,42.42) v1(74.295,42.42) 77.928,42.42 77.933,42.425 v1(85.625,42.425) ; v1(85.075,61.925) 85.104,61.896 96.95,61.896 97.346,61.5 113.475,61.5 v1(113.925,61.95) 147.475,61.95 v1(147.5,61.925)
  Bottom Layer w0.12: v1(11.425,24) v1(11.425,27.15) v1(11.425,42.725) ; R151.1@15.025,13.725 16.525,13.725 16.775,13.975 16.775,17.725 16.05,18.45 16.05,22.477 16.055,22.482 16.055,22.818 16.05,22.823 v1(16.05,23.325) ; v1(32.125,42.42) v1(32.125,50.15) ; v1(74.295,33.58) v1(74.295,42.42) ; v1(85.625,42.425) 85.625,56.976 85.427,57.175 85.427,60.954 85.43,60.957 85.43,61.57 v1(85.075,61.925) 85.075,62.975 85.225,63.125 85.225,84.725 85.375,84.875 85.375,85.725 85.65,86 SB44.2@86.4,86 ; v1(113.625,50.05) 113.278,50.397 113.278,61.303 v1(113.925,61.95) ; v1(147.5,61.925) U31.1@147.5,65.75 B1.3@149.925,65.75 B1.4@149.925,75.25
OCSPI1_CLK: R83.1 U10.B2 | length 3.6
  Top Layer w0.127: U10.B2@63.775,35.55 65.3,37.075 R83.1@65.3,38.475
OCSPI1_DQS: R101.1 U10.C3 | length 4.1
  Top Layer w0.127: U10.C3@62.775,34.55 63.275,34.05 63.275,30.75 R101.1@63.375,30.65
OCSPI1_IO0: R95.2 U10.D3 | length 4.6
  Top Layer w0.127: R95.2@57.9,33.775 58.875,33.775 60.125,35.025 61.3,35.025 U10.D3@61.775,34.55
OCSPI1_IO1: R91.2 U10.D2 | length 4.1
  Top Layer w0.127: R91.2@57.9,35.975 57.975,36.05 61.275,36.05 U10.D2@61.775,35.55
OCSPI1_IO2: R100.1 U10.C4 | length 3.1
  Top Layer w0.127: R100.1@62.3,30.65 62.25,30.7 62.25,33.025 U10.C4@62.775,33.55
OCSPI1_IO3: R98.2 U10.D4 | length 3.6
  Top Layer w0.127: R98.2@60.15,30.65 60.15,31.1 61.25,32.2 61.25,33.025 U10.D4@61.775,33.55
OCSPI1_IO4: R99.2 U10.D5 | length 2.1
  Top Layer w0.127: R99.2@61.225,30.65 61.225,31.45 61.775,32 U10.D5@61.775,32.55
OCSPI1_IO5: R96.2 U10.E3 | length 3.7
  Top Layer w0.127: R96.2@57.9,32.65 58.354,32.65 60.254,34.55 U10.E3@60.775,34.55
OCSPI1_IO6: R93.2 U10.E2 | length 3.1
  Top Layer w0.127: R93.2@57.9,34.9 59,34.9 59.65,35.55 U10.E2@60.775,35.55
OCSPI1_IO7: R87.2 U10.E1 | length 3.1
  Top Layer w0.127: R87.2@57.9,37.05 60.275,37.05 U10.E1@60.775,36.55
OCSPI1_NCS: R81.1 R82.2 U10.C2 | length 4.3
  Top Layer w0.127: U10.C2@62.775,35.55 63.3,36.075 63.3,38.325 R81.1@63.15,38.475 R82.2@64.225,38.475
OCSPI2_CLK: R60.1 U7.B2 | length 3.1
  Top Layer w0.127: U7.B2@35.05,55.425 35.825,54.65 R60.1@37.85,54.65
OCSPI2_DQS: R53.1 U7.C3 | length 4
  Top Layer w0.127: U7.C3@34.05,56.425 34.55,55.925 37.825,55.925 R53.1@37.85,55.9
OCSPI2_IO0: R37.1 U7.D3 | length 4.2
  Top Layer w0.127: R37.1@32.975,61.225 32.975,60.1 33.55,59.525 33.55,57.925 U7.D3@34.05,57.425
OCSPI2_IO1: R46.1 U7.D2 | length 3
  Top Layer w0.127: U7.D2@35.05,57.425 35.55,57.925 37.75,57.925 R46.1@37.85,58.025
OCSPI2_IO2: R52.1 U7.C4 | length 3.1
  Top Layer w0.127: R52.1@30.15,56.025 30.25,55.925 32.55,55.925 U7.C4@33.05,56.425
OCSPI2_IO3: R45.1 U7.D4 | length 3.4
  Top Layer w0.127: R45.1@30.15,58.6 30.9,58.6 31.575,57.925 32.55,57.925 U7.D4@33.05,57.425
OCSPI2_IO4: R48.2 U7.D5 | length 1.9
  Top Layer w0.127: R48.2@30.15,57.35 30.225,57.425 U7.D5@32.05,57.425
OCSPI2_IO5: R38.2 U7.E3 | length 2.8
  Top Layer w0.127: U7.E3@34.05,58.425 R38.2@34.05,61.225
OCSPI2_IO6: R39.2 U7.E2 | length 2.8
  Top Layer w0.127: U7.E2@35.05,58.425 35.05,61.15 R39.2@35.125,61.225
OCSPI2_IO7: R40.2 U7.E1 | length 2.9
  Top Layer w0.127: U7.E1@36.05,58.425 36.05,61.075 R40.2@36.2,61.225
OCSPI2_NCS: R65.1 R66.2 U7.A3 | length 4.1
  Top Layer w0.127: U7.A3@34.05,54.425 34.05,53.025 34.525,52.55 R65.1@34.525,51.65 35.695,51.65 R66.2@35.7,51.645
OSC_25M: R35.1 R68.1 | length 59.5
  Top Layer w0.127: R35.1@76.975,63.75 77.575,63.75 v1(77.875,63.45) ; R68.1@122,50.55 v1(122.725,50.55)
  Signal Layer 3 w0.102: v1(77.875,63.45) v1(122.725,63.45)
  Bottom Layer w0.127: v1(122.725,50.55) v1(122.725,63.45)
PC14: R62.1 U6.D2 | length 8
  Top Layer w0.1: U6.D2@71.2,58.575 71.425,58.575 71.725,58.275 72.425,58.275 73.375,57.325 73.375,55.225 75.075,53.525 75.425,53.525
  Top Layer w0.127: 75.425,53.525 R62.1@75.925,53.525
PC15: R54.1 U6.D1 | length 6.8
  Top Layer w0.1: U6.D1@71.85,58.575 72.55,58.575 73.65,57.475 73.65,55.45 74.125,54.975 75.425,54.975
  Top Layer w0.127: 75.425,54.975 R54.1@75.925,54.975
PF6: CN4.3 SB10.1 SB17.1 SB29.2 U6.H1 U12.E4 | length 218.2
  Top Layer w0.09: 38.475,34.906 38.475,33.375 U12.E4@38.725,33.125
  Top Layer w0.1: 38.475,34.906 38.475,35.225 v1(39.075,35.825) ; U6.H1@71.85,61.175 73.725,61.175 74.025,61.475 74.925,61.475 v1(75.575,62.125)
  Top Layer w0.12: v1(15.325,65.15) 13.825,66.65 13.825,69.4 v1(15.325,70.9) ; SB29.2@51.875,24.45 51.875,25.675 v1(52.839,26.639) ; v1(125.984,38.864) CN4.3@127.801,38.864
  Signal Layer 3 w0.1: 33.2,35.825 v1(39.075,35.825)
  Signal Layer 3 w0.12: v1(12.625,35.825) 33.2,35.825 ; v1(15.325,65.15) v1(16.5,65.15) ; v1(40.65,26.3) 45.75,26.3 46.089,26.639 v1(52.839,26.639) v1(83.5,26.639) ; v1(75.575,62.125) 75.58,62.13 83.12,62.13 v1(83.5,61.75) ; v1(83.5,38.864) v1(125.984,38.864)
  Bottom Layer w0.1: v1(39.075,35.825) 39.075,34.775 40.65,33.2 40.65,27.5
  Bottom Layer w0.12: v1(12.625,35.825) 12.625,39.95 15.625,42.95 15.625,48.225 16.5,49.1 v1(16.5,65.15) ; SB10.1@14.2,65.15 v1(15.325,65.15) ; SB17.1@14.2,70.9 v1(15.325,70.9) ; v1(40.65,26.3) 40.65,27.5 ; v1(83.5,26.639) v1(83.5,38.864) v1(83.5,61.75)
PF7: CN4.6 SB7.1 SB14.1 SB25.2 SB30.2 U6.J3 U12.D3 | length 226.7
  Top Layer w0.12: v1(15.325,62.275) 15.984,62.934 15.984,67.366 v1(15.325,68.025) ; SB30.2@55.675,24.45 v1(55.675,27.125) ; CN4.6@124.372,46.484 v1(126.188,46.484) 133.581,46.484 SB25.2@133.586,46.489
  Top Layer w0.127: U6.J3@70.55,61.825 v2(70.875,61.5)
  Signal Layer 1 w0.1: v2(39.225,32.625) v1(42.45,32.625) ; v2(70.875,61.5) 74.825,61.5 75.425,60.9 ; v1(74.45,59.375) 75.25,59.375 75.425,59.55
  Signal Layer 1 w0.12: 75.425,59.55 75.5,59.625 75.5,60.825 75.425,60.9
  Signal Layer 3 w0.1: 33.2,32.625 v1(42.45,32.625)
  Signal Layer 3 w0.12: v1(12,34.225) 23.85,34.225 25.45,32.625 33.2,32.625 ; v1(42.4,26.75) 45.2,26.75 45.575,27.125 v1(55.675,27.125) v1(82.925,27.125) ; v1(74.45,59.375) v1(82.925,59.375) ; v1(82.925,46.484) 88.641,46.484 92.725,42.4 122.104,42.4 v1(126.188,46.484)
  Bottom Layer w0.12: v1(12,34.225) 12,40.225 15.125,43.35 15.125,48.35 15.625,48.85 15.625,60.408 15.896,60.68 15.896,61.704 v1(15.325,62.275) SB7.1@14.2,62.275 ; SB14.1@14.2,68.025 v1(15.325,68.025) ; v1(42.4,26.75) 42.4,28.6 41.975,29.025 41.975,32.15 v1(42.45,32.625) ; v1(82.925,27.125) v1(82.925,46.484) v1(82.925,59.375)
PMOD1: P1.1 P2.1 SB15.2 SB17.2 | length 24.4
  Signal Layer 3 w0.12: P2.1@9.975,72 12.5,72 13.975,73.475 26.445,73.475 P1.1@28.05,75.08
  Bottom Layer w0.12: P2.1@9.95,72 P2.1@9.975,72 11.15,72 12.25,70.9 13.075,70.9 SB15.2@13.075,69.45
PMOD2: P1.2 P2.2 SB12.2 SB14.2 | length 25.2
  Signal Layer 3 w0.12: P2.2@9.975,70 12.375,70 14.375,72 v1(25.2,72)
  Bottom Layer w0.12: P2.2@9.95,70 P2.2@9.975,70 11.25,70 11.975,69.275 11.975,68.275 12.225,68.025 13.075,68.025 SB12.2@13.075,66.575 ; v1(25.2,72) 25.2,72.9 25.51,73.21 P1.2@25.51,75.08
PMOD3: P1.3 P2.3 SB8.2 SB10.2 | length 25.4
  Signal Layer 3 w0.12: P2.3@9.975,68 13.7,68 14.425,68.725 18.425,68.725 20.2,70.5 v1(22.97,70.5)
  Bottom Layer w0.12: P2.3@9.95,68 P2.3@9.975,68 11.25,68 11.85,67.4 11.85,65.55 12.25,65.15 13.075,65.15 SB8.2@13.075,63.7 ; v1(22.97,70.5) P1.3@22.97,75.08
PMOD4: P1.4 P2.4 SB6.2 SB7.2 | length 25.9
  Signal Layer 3 w0.12: P2.4@9.975,66 17.525,66 18.175,66.65 19.45,66.65 v1(20.625,67.825)
  Bottom Layer w0.12: P2.4@9.95,66 11.6,64.35 11.6,62.5 11.825,62.275 13.075,62.275 SB6.2@13.075,60.825 ; P1.4@20.43,75.08 20.43,72.595 20.625,72.4 v1(20.625,67.825)
PMOD11: P1.7 P2.11 U6.N15 | length 69.9
  Top Layer w0.1: 59.206,68.123 60.55,66.778 60.55,66.233 62.358,64.425 U6.N15@62.75,64.425
  Top Layer w0.12: v1(58.502,75.075) 58.502,68.826 59.206,68.123
  Signal Layer 3 w0.12: P2.11@7.975,72 7.975,75.125 12.3,79.45 26.22,79.45 P1.7@28.05,77.62 35.355,77.62 37.9,75.075 v1(58.502,75.075)
PMOD12: P1.8 P2.12 U6.K1 | length 91.4
  Top Layer w0.1: U6.K1@71.85,62.475 72.45,62.475 72.95,62.975 73.6,62.975 v1(74,62.575)
  Signal Layer 3 w0.1: P2.12@7.975,70 8.975,69 11.025,69 ; 59.175,62.725 59.4,62.95 60.55,62.95 60.8,62.7 65.57,62.7 65.662,62.792 68.567,62.792 69.025,63.25 73.325,63.25 v1(74,62.575)
  Signal Layer 3 w0.12: 11.025,69 12.85,69 13.975,70.125 16.925,70.125 17.8,71 v1(20.1,71) v1(23.775,71) ; v1(20.1,61.75) 20.465,62.115 30.806,62.115 31.081,61.84 51.619,61.84 51.754,61.975 58.425,61.975 59.175,62.725
  Bottom Layer w0.12: v1(20.1,61.75) v1(20.1,71) ; v1(23.775,71) 23.775,73 24.25,73.475 24.25,76.36 P1.8@25.51,77.62
PMOD17: CN20.6 P2.17 U6.P9 | length 96.9
  Top Layer w0.1: 66.325,69.075 66.325,65.4 U6.P9@66.65,65.075
  Top Layer w0.12: 66.325,69.075 66.325,72.4 v1(66.775,72.85)
  Signal Layer 3 w0.1: P2.17@7.975,60 8.975,59 11.025,59
  Signal Layer 3 w0.12: 11.025,59 11.164,59 12.364,60.2 v1(24.375,60.2) ; v1(24.375,72.475) 61.55,72.475 62.13,73.055 63.545,73.055 63.75,72.85 v1(66.775,72.85)
  Bottom Layer w0.12: CN20.6@6.425,45.212 5.15,46.487 5.15,57.175 P2.17@7.975,60 ; v1(24.375,60.2) v1(24.375,72.475)
PMOD18: CN20.3 CN20.4 P2.18 U6.R11 | length 97
  Top Layer w0.1: U6.R11@65.35,65.725 v1(65.35,67.475)
  Signal Layer 3 w0.1: P2.18@7.975,58 8.975,57 11.025,57
  Signal Layer 3 w0.12: 11.025,57 11.375,57 13.375,59 v1(24.875,59) ; v1(25.325,71) v1(32.95,71) ; v1(32.95,74.575) 62.043,74.575 62.468,75 v1(64.675,75)
  Bottom Layer w0.1: 64.675,69.075 64.675,68.15 v1(65.35,67.475)
  Bottom Layer w0.12: CN20.3@7.695,46.482 CN20.4@6.425,46.482 5.675,47.232 5.675,55.7 P2.18@7.975,58 ; v1(24.875,59) 24.875,68.9 25.325,69.35 v1(25.325,71) ; v1(32.95,71) v1(32.95,74.575) ; 64.675,69.075 v1(64.675,75)
PMOD19: CN20.5 P2.19 U6.R9 | length 94.2
  Top Layer w0.1: U6.R9@66.65,65.725 66.65,66.475 66.539,66.587 66.539,68.963 66.65,69.075
  Top Layer w0.127: 66.65,69.075 66.698,69.123 66.698,70.152 66.775,70.229 v1(66.775,72.2)
  Signal Layer 3 w0.1: P2.19@7.975,56 8.975,55 11.025,55
  Signal Layer 3 w0.12: 11.025,55 11.2,55 12.75,56.55 v1(25.725,56.55) ; v1(25.93,72.03) 30.68,72.03 30.85,72.2 v1(66.775,72.2)
  Bottom Layer w0.12: CN20.5@7.695,45.212 8.725,46.242 8.725,51.25 6.725,53.25 6.725,54.75 P2.19@7.805,55.83 ; v1(25.725,56.55) 25.725,63.827 25.93,64.032 v1(25.93,72.03)
PMOD20: CN20.7 P2.20 U6.N11 | length 92.8
  Top Layer w0.127: v2(65.025,64.75) U6.N11@65.35,64.425
  Signal Layer 1 w0.1: v2(65.025,64.75) 65.8,65.525 65.8,67.875 65.103,68.572 65.103,69.953 v1(65.575,70.425)
  Signal Layer 3 w0.12: P2.20@7.975,54 9.175,52.8 12.2,52.8 13.625,54.225 v1(26.3,54.225) ; v1(27.25,69.775) 27.7,70.225 34.125,70.225 34.38,69.97 53.595,69.97 54.05,70.425 61.127,70.425 61.132,70.42 65.57,70.42 v1(65.575,70.425)
  Bottom Layer w0.12: CN20.7@7.695,43.942 8.742,43.942 9.075,44.275 9.075,52.9 P2.20@7.975,54 ; v1(26.3,54.225) 26.3,66.575 27.25,67.525 v1(27.25,69.775)
POE1: C1.1 C2.1 C7.1 C18.1 C28.1 C30.1 C39.1 C42.1 C52.1 D7.2 R43.1 R44.1 R61.1 T1.4 T2.1 U2.3 U8.9 | length 30.5
  Top Layer w0.4: U8.9@104.851,53.996 106.116,53.996 R61.1@106.157,54.037 ; C52.1@106.157,49.846 v1(106.157,50.643)
  Top Layer w0.5: v1(97.725,67.339) 97.725,66.394 C30.1@97.8,66.319 ; C30.1@98.159,65.91 98.6,66.351 v1(98.6,67.339)
  Top Layer w0.6: T2.1@94.48,83.005 96.62,83.005 97.37,82.255 T1.4@97.603,82.255 v1(98.97,82.255) ; C30.1@97.8,66.319 97.775,66.294 C30.1@98.159,65.91 99.46,65.91 99.886,66.336 C28.1@99.886,67.839 99.471,68.254 U2.3@98.136,68.254 ; R44.1@98.011,58.689 v1(98.011,57.539) C39.1@100.461,57.539 ; C7.1@98.736,85.289 v1(98.736,86.286) ; C1.1@101.461,85.789 v1(101.461,86.936) ; v1(102.1,75.375) 102.601,75.375 C18.1@103.061,74.914 ; C2.1@104.586,85.789 v1(104.586,86.936) ; C42.1@105.961,57.539 v1(106.914,57.539) ; v1(106.975,55.075) 106.157,54.257 R61.1@106.157,54.037 106.419,53.775 108.076,53.775 D7.2@108.836,53.014 ; v1(109.811,58.011) R43.1@109.811,59.514
POE2: R4.2 T1.3 T2.2 | length 6.5
  Top Layer w0.6: T2.2@94.48,80.505 94.73,80.255 T1.3@97.603,80.255 98.73,80.255 99.475,81 100.297,81 R4.2@100.511,81.214
POE3: R5.2 T1.2 T2.3 T4.2 T4.4 | length 27.5
  Top Layer w0.6: T2.3@94.48,78.005 94.601,78.125 T1.2@97.245,78.125 ; T1.2@97.603,78.255 98.03,78.255 98.889,79.114 R5.2@100.086,79.114 100.086,78.664 v1(99.297,77.875)
  Top Layer w1: 102.75,67.8 103.1,67.8 104.841,67.8 T4.4@105.169,68.128 T4.2@105.169,61.778
  Bottom Layer w1: v1(99.297,77.875) 99.297,71.003 v1(102.5,67.8)
POE4: C14.2 C18.2 L1.1 T1.1 T2.4
POE5: D2.1 R7.1 T1.7 T1.8 T2.5 T2.6 | length 6.4
  Top Layer w0.12: D2.1@78.706,76.214 D2.1@78.711,76.219 ; T2.5@83.05,75.505 83.4,75.855 85.623,75.855 T1.8@86.023,76.255 ; T2.6@83.05,78.005 83.3,78.255 T1.7@86.023,78.255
